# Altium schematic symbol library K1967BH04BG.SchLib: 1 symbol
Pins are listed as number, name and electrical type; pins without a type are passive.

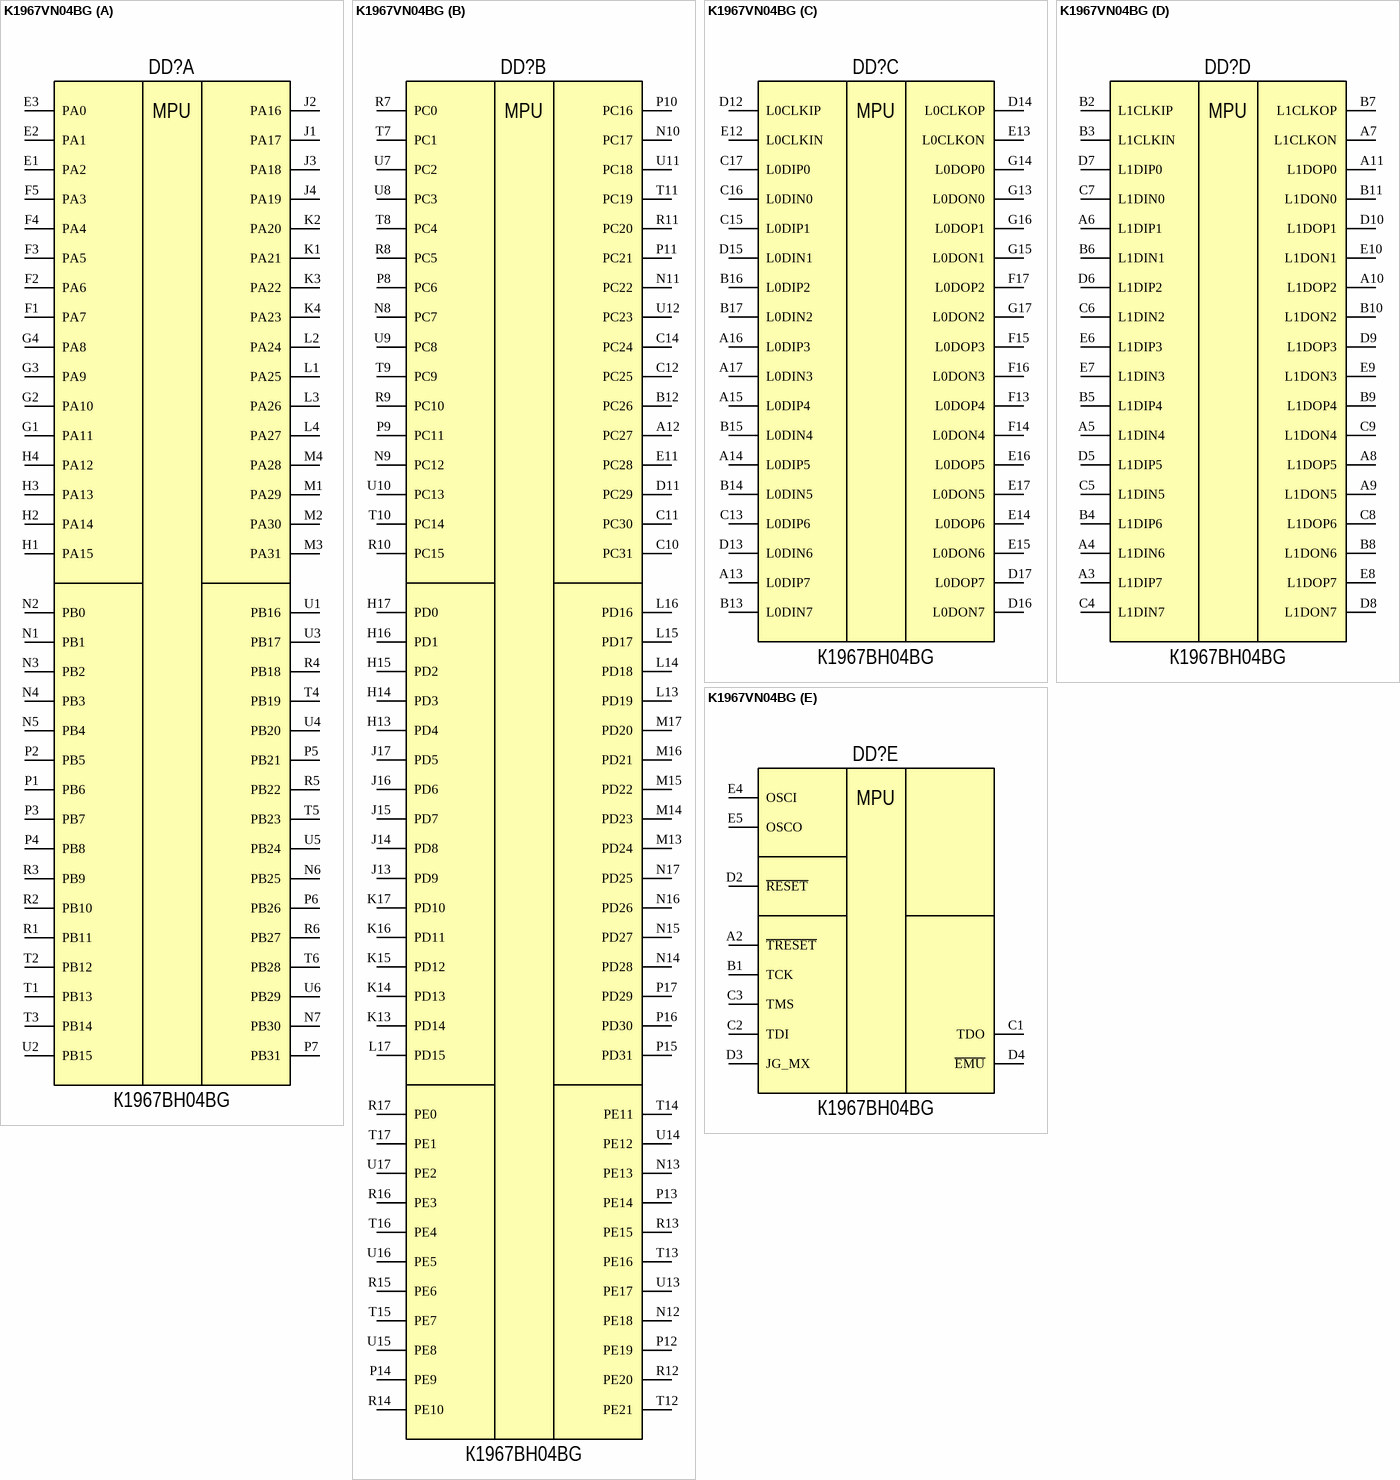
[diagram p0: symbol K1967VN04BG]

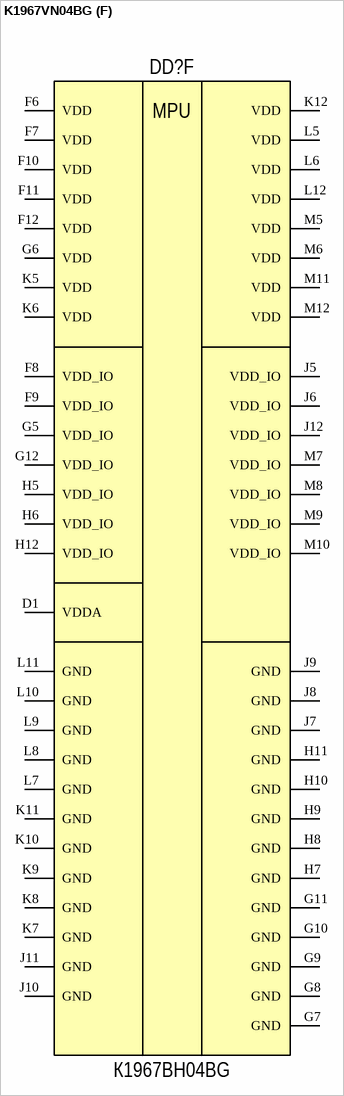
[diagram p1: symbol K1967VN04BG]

## K1967VN04BG
designator DD?
part A pins: E1 PA2, E2 PA1, E3 PA0, F1 PA7, F2 PA6, F3 PA5, F4 PA4, F5 PA3, G1 PA11, G2 PA10, G3 PA9, G4 PA8, H1 PA15, H2 PA14, H3 PA13, H4 PA12, J1 PA17, J2 PA16, J3 PA18, J4 PA19, K1 PA21, K2 PA20, K3 PA22, K4 PA23, L1 PA25, L2 PA24, L3 PA26, L4 PA27, M1 PA29, M2 PA30, M3 PA31, M4 PA28, N1 PB1, N2 PB0, N3 PB2, N4 PB3, N5 PB4, N6 PB25, N7 PB30, P1 PB6, P2 PB5, P3 PB7, P4 PB8, P5 PB21, P6 PB26, P7 PB31, R1 PB11, R2 PB10, R3 PB9, R4 PB18, R5 PB22, R6 PB27, T1 PB13, T2 PB12, T3 PB14, T4 PB19, T5 PB23, T6 PB28, U1 PB16, U2 PB15, U3 PB17, U4 PB20, U5 PB24, U6 PB29
part B pins: A12 PC27, B12 PC26, C10 PC31, C11 PC30, C12 PC25, C14 PC24, D11 PC29, E11 PC28, H13 PD4, H14 PD3, H15 PD2, H16 PD1, H17 PD0, J13 PD9, J14 PD8, J15 PD7, J16 PD6, J17 PD5, K13 PD14, K14 PD13, K15 PD12, K16 PD11, K17 PD10, L13 PD19, L14 PD18, L15 PD17, L16 PD16, L17 PD15, M13 PD24, M14 PD23, M15 PD22, M16 PD21, M17 PD20, N8 PC7, N9 PC12, N10 PC17, N11 PC22, N12 PE18, N13 PE13, N14 PD28, N15 PD27, N16 PD26, N17 PD25, P8 PC6, P9 PC11, P10 PC16, P11 PC21, P12 PE19, P13 PE14, P14 PE9, P15 PD31, P16 PD30, P17 PD29, R7 PC0, R8 PC5, R9 PC10, R10 PC15, R11 PC20, R12 PE20, R13 PE15, R14 PE10, R15 PE6, R16 PE3, R17 PE0, T7 PC1, T8 PC4, T9 PC9, T10 PC14, T11 PC19, T12 PE21, T13 PE16, T14 PE11, T15 PE7, T16 PE4, T17 PE1, U7 PC2, U8 PC3, U9 PC8, U10 PC13, U11 PC18, U12 PC23, U13 PE17, U14 PE12, U15 PE8, U16 PE5, U17 PE2
part C pins: A13 L0DIP7, A14 L0DIP5, A15 L0DIP4, A16 L0DIP3, A17 L0DIN3, B13 L0DIN7, B14 L0DIN5, B15 L0DIN4, B16 L0DIP2, B17 L0DIN2, C13 L0DIP6, C15 L0DIP1, C16 L0DIN0, C17 L0DIP0, D12 L0CLKIP, D13 L0DIN6, D14 L0CLKOP, D15 L0DIN1, D16 L0DON7, D17 L0DOP7, E12 L0CLKIN, E13 L0CLKON, E14 L0DOP6, E15 L0DON6, E16 L0DOP5, E17 L0DON5, F13 L0DOP4, F14 L0DON4, F15 L0DOP3, F16 L0DON3, F17 L0DOP2, G13 L0DON0, G14 L0DOP0, G15 L0DON1, G16 L0DOP1, G17 L0DON2
part D pins: A3 L1DIP7, A4 L1DIN6, A5 L1DIN4, A6 L1DIP1, A7 L1CLKON, A8 L1DOP5, A9 L1DON5, A10 L1DOP2, A11 L1DOP0, B2 L1CLKIP, B3 L1CLKIN, B4 L1DIP6, B5 L1DIP4, B6 L1DIN1, B7 L1CLKOP, B8 L1DON6, B9 L1DOP4, B10 L1DON2, B11 L1DON0, C4 L1DIN7, C5 L1DIN5, C6 L1DIN2, C7 L1DIN0, C8 L1DOP6, C9 L1DON4, D5 L1DIP5, D6 L1DIP2, D7 L1DIP0, D8 L1DON7, D9 L1DOP3, D10 L1DOP1, E6 L1DIP3, E7 L1DIN3, E8 L1DOP7, E9 L1DON3, E10 L1DON1
part E pins: A2 ~{TRESET}, B1 TCK, C1 TDO, C2 TDI, C3 TMS, D2 ~{RESET}, D3 JG_MX, D4 ~{EMU}, E4 OSCI, E5 OSCO
part F pins: D1 VDDA (power), F6 VDD (power), F7 VDD (power), F8 VDD_IO (power), F9 VDD_IO (power), F10 VDD (power), F11 VDD (power), F12 VDD (power), G5 VDD_IO (power), G6 VDD (power), G7 GND (power), G8 GND (power), G9 GND (power), G10 GND (power), G11 GND (power), G12 VDD_IO (power), H5 VDD_IO (power), H6 VDD_IO (power), H7 GND (power), H8 GND (power), H9 GND (power), H10 GND (power), H11 GND (power), H12 VDD_IO (power), J5 VDD_IO (power), J6 VDD_IO (power), J7 GND (power), J8 GND (power), J9 GND (power), J10 GND (power), J11 GND (power), J12 VDD_IO (power), K5 VDD (power), K6 VDD (power), K7 GND (power), K8 GND (power), K9 GND (power), K10 GND (power), K11 GND (power), K12 VDD (power), L5 VDD (power), L6 VDD (power), L7 GND (power), L8 GND (power), L9 GND (power), L10 GND (power), L11 GND (power), L12 VDD (power), M5 VDD (power), M6 VDD (power), M7 VDD_IO (power), M8 VDD_IO (power), M9 VDD_IO (power), M10 VDD_IO (power), M11 VDD (power), M12 VDD (power)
